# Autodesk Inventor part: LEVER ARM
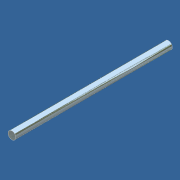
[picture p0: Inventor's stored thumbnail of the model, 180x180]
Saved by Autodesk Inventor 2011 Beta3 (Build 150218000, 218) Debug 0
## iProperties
Shininess: 64.0
Length Units: 11272
Angle Units: 11279
Time Units: 11290
Mass Units: 11286
Length Display Precision: 3
Angle Display Precision: 2
Compacted: True
Part Number: LEVER ARM
Document SubType Name: Modeling
Created: 2003-11
Designer: Autodesk, Inc.
Manufacturer: Standard
Standards Organization: Custom
Mass: 252.903 g
Surface Area: 103.875 cm^2
Volume: 32.1759 cm^3
Density: 7.86 g/cm^3
Material: Steel, Mild
Density: 0.0
Volumn: 0.0
Area: 0.0
PropertySet Name: Model Information
Control State: 0
Master: False
Checked Out: False
Author: Autodesk, Inc.
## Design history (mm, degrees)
sketch "Sketch1"
  geometry: C1 r 6.35 at (0, 0); 1 further point
  constraints: 1 centre point, 1 coincident
  dimensions: "d0" = 12.7 diameter of C1
extrude "Extrusion1" new body sketch "Sketch1" distance "d1" = 254; taper "d2" = 0 deg
workplane "Work Plane1"
body "Solid1"
